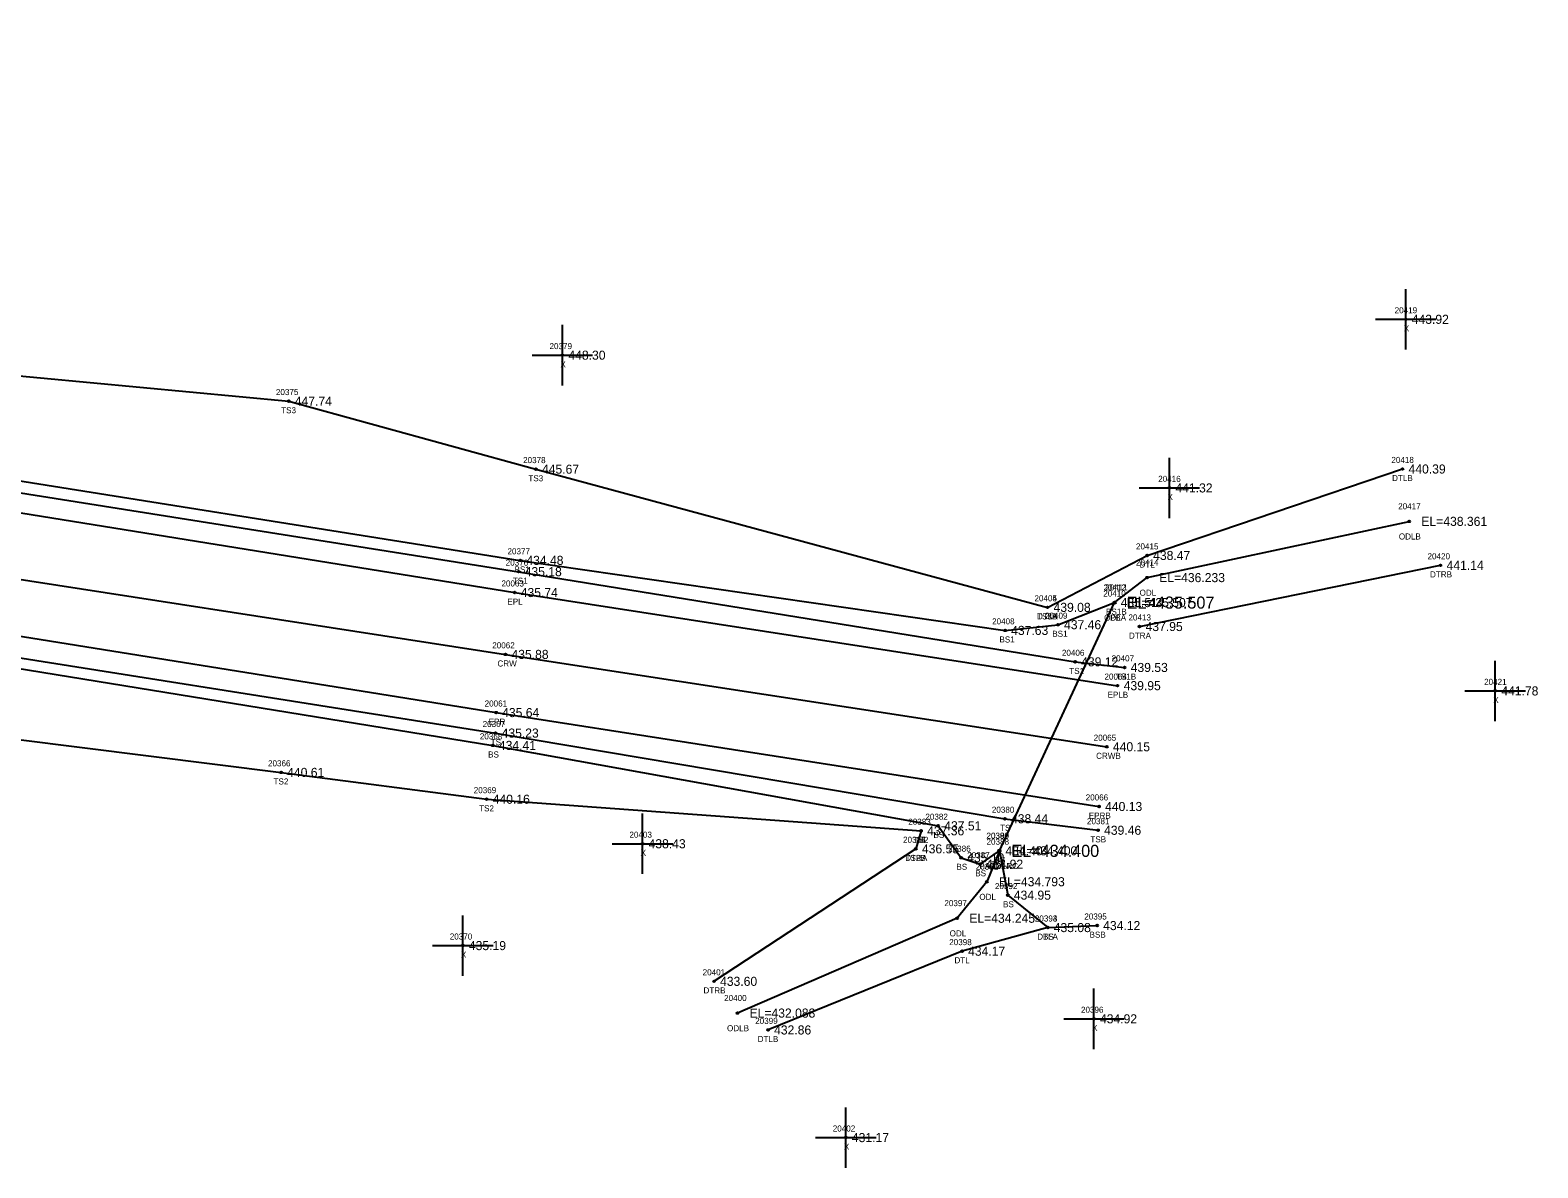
# Model space of a CAD drawing. Extents: x 1613184 to 1614731, y 770859 to 771868.
# Drawn here: x 1614482.1 to 1614731.4, y 771158.6 to 771346.7 of the extents above; entities that cross this region are included whole.
import ezdxf

# ---------------------------------------------------------------- set-up
doc = ezdxf.new("R2010")
doc.units = 0
for name, color, linetype in [('Default', 7, 'Continuous'), ('RD_DTM_BkLn1', 7, 'Continuous'), ('RD_DTM_BkLn2', 7, 'Continuous'), ('RD_DTM_BkLn_txCode', 7, 'Continuous'), ('RD_EX_DR_Pipe_txCode', 7, 'Continuous'), ('RD_EX_H2O', 7, 'Continuous'), ('RD_EX_H2O_txCode', 7, 'Continuous'), ('RD_EX_Misc', 7, 'Continuous'), ('RD_EX_Misc_txCode', 7, 'Continuous'), ('RD_EX_Road', 7, 'Continuous'), ('RD_EX_Road_txCode', 7, 'Continuous'), ('RD_EX_TX_H2O_ELEV', 7, 'Continuous'), ('RD_EX_TX_Misc_ELEV', 7, 'Continuous'), ('RD_EX_TX_Road_ELEV', 7, 'Continuous'), ('RD_HC_Survey_ELEV', 7, 'Continuous'), ('RD_HC_Survey_txCode', 7, 'Continuous'), ('RD_SMD_Locator', 7, 'Continuous'), ('RD_TX_Pipe_ElevEX', 7, 'Continuous')]:
    doc.layers.add(name, color=color, linetype=linetype)

msp = doc.modelspace()

# ---------------------------------------------------------------- linework, layer by layer
at = {"layer": 'Default'}
msp.add_line((1614642.36, 771211.01), (1614661.41, 771252.06), dxfattribs=at)
at = {"layer": 'RD_DTM_BkLn1'}
msp.add_lwpolyline([(1613965.11, 771336.88), (1614064.55, 771323.02), (1614163.88, 771306.86), (1614262.51, 771291.89), (1614361.57, 771275.2), (1614461.76, 771258.77), (1614560.71, 771243.49), (1614660.13, 771228.22)], dxfattribs=at)
at = {"layer": 'RD_DTM_BkLn2'}
for points in [[(1613964.19, 771322.73), (1613968.82, 771317.98), (1613995.59, 771312.64), (1614063.18, 771305.5), (1614161.48, 771291.91), (1614259.01, 771275.6), (1614358.23, 771261.08), (1614459.56, 771246.25), (1614559.08, 771230.48), (1614643.28, 771216.31), (1614658.67, 771214.41)], [(1613942.37, 771316.04), (1613958.6, 771307.1), (1613993.85, 771297.11), (1614061.98, 771289.14), (1614161.12, 771278.24), (1614255.97, 771263.05), (1614304.44, 771258.76), (1614327.58, 771260.25), (1614357.86, 771257.94), (1614459.3, 771244.57), (1614558.63, 771228.44), (1614632.25, 771215.15), (1614636.04, 771209.87), (1614639.16, 771208.8), (1614642.36, 771211.01), (1614643.75, 771203.68), (1614650.35, 771198.32), (1614658.52, 771198.65)], [(1614279.01, 771313.26), (1614281.2, 771317.14), (1614295.57, 771311.48), (1614364.56, 771299.51), (1614467.36, 771290.78), (1614524.89, 771285.37), (1614565.75, 771274.12), (1614650.32, 771251.27)], [(1614279.01, 771313.26), (1614280.58, 771310.17), (1614294.3, 771303.5), (1614363.28, 771288.72), (1614464.52, 771272.74), (1614562.89, 771257.17), (1614654.88, 771242.26), (1614663.07, 771241.33)], [(1614281.21, 771312.71), (1614294.52, 771307.09), (1614363.85, 771291.82), (1614464.84, 771274.67), (1614563.17, 771259.04), (1614643.31, 771247.46), (1614652.05, 771248.4), (1614661.41, 771252.06)], [(1614308.13, 771255.96), (1614327.93, 771256.05), (1614357.76, 771255.48), (1614457.77, 771232.22), (1614523.63, 771223.98), (1614557.61, 771219.54), (1614629.42, 771214.32), (1614628.56, 771211.34)]]:
    msp.add_lwpolyline(points, dxfattribs=at)
at = {"layer": 'RD_EX_H2O'}
for p, q in [((1614665.53, 771248.1), (1614715.29, 771258.22)), ((1614628.56, 771211.34), (1614595.19, 771189.43))]:
    msp.add_line(p, q, dxfattribs=at)
for points in [[(1614650.32, 771251.27), (1614666.78, 771259.85), (1614709, 771274.15)], [(1614661.41, 771252.06), (1614666.78, 771256.19), (1614710.12, 771265.49)], [(1614642.36, 771211.01), (1614640.3, 771205.9), (1614635.39, 771199.86), (1614599.06, 771184.18)], [(1614650.35, 771198.32), (1614636.19, 771194.41), (1614604.12, 771181.39)]]:
    msp.add_lwpolyline(points, dxfattribs=at)
at = {"layer": 'RD_EX_Misc'}
for p, q in [((1614709.53, 771293.9), (1614709.53, 771303.9)), ((1614704.53, 771298.9), (1614714.53, 771298.9)), ((1614570.12, 771287.97), (1614570.12, 771297.97)), ((1614565.12, 771292.97), (1614575.12, 771292.97)), ((1614670.47, 771266.02), (1614670.47, 771276.02)), ((1614665.47, 771271.02), (1614675.47, 771271.02)), ((1614724.33, 771232.45), (1614724.33, 771242.45)), ((1614719.33, 771237.45), (1614729.33, 771237.45)), ((1614583.37, 771207.18), (1614583.37, 771217.18)), ((1614578.37, 771212.18), (1614588.37, 771212.18)), ((1614553.67, 771190.34), (1614553.67, 771200.34)), ((1614548.67, 771195.34), (1614558.67, 771195.34)), ((1614657.99, 771178.23), (1614657.99, 771188.23)), ((1614652.99, 771183.23), (1614662.99, 771183.23)), ((1614616.98, 771158.59), (1614616.98, 771168.59)), ((1614611.98, 771163.59), (1614621.98, 771163.59))]:
    msp.add_line(p, q, dxfattribs=at)
at = {"layer": 'RD_EX_Road'}
for points in [[(1613966.21, 771346.72), (1614065.91, 771332.61), (1614166, 771316.74), (1614252.8, 771303.53), (1614264.27, 771301.76), (1614271.95, 771300.8), (1614363.43, 771285.99), (1614463.49, 771269.68), (1614562.24, 771253.72), (1614661.91, 771238.32)], [(1613963.41, 771324.71), (1614062.98, 771312.73), (1614162.48, 771297.04), (1614260.87, 771281.9), (1614360.23, 771265.95), (1614460.24, 771249.77), (1614559.17, 771233.87), (1614658.84, 771218.34)]]:
    msp.add_lwpolyline(points, dxfattribs=at)
at = {"layer": 'RD_SMD_Locator'}
for centre, radius in [((1614709.53, 771298.9), 0.15), ((1614570.12, 771292.97), 0.15), ((1614524.89, 771285.37), 0.15), ((1614565.75, 771274.12), 0.15), ((1614709, 771274.15), 0.15), ((1614670.47, 771271.02), 0.15), ((1614710.12, 771265.49), 0.15), ((1614563.17, 771259.04), 0.15), ((1614666.78, 771259.85), 0.15), ((1614562.89, 771257.17), 0.15), ((1614666.78, 771256.19), 0.15), ((1614715.29, 771258.22), 0.15), ((1614562.24, 771253.72), 0.15), ((1614650.32, 771251.27), 0.15), ((1614650.32, 771251.27), 0.15), ((1614661.41, 771252.06), 0.2), ((1614661.41, 771252.06), 0.15), ((1614661.41, 771252.06), 0.15), ((1614652.05, 771248.4), 0.15), ((1614643.31, 771247.46), 0.15), ((1614665.53, 771248.1), 0.15), ((1614560.71, 771243.49), 0.15), ((1614654.88, 771242.26), 0.15), ((1614663.07, 771241.33), 0.15), ((1614661.91, 771238.32), 0.15), ((1614724.33, 771237.45), 0.15), ((1614559.17, 771233.87), 0.15), ((1614558.63, 771228.44), 0.15), ((1614559.08, 771230.48), 0.15), ((1614660.13, 771228.22), 0.15), ((1614523.63, 771223.98), 0.15), ((1614557.61, 771219.54), 0.15), ((1614643.28, 771216.31), 0.15), ((1614658.84, 771218.34), 0.15), ((1614629.42, 771214.32), 0.15), ((1614632.25, 771215.15), 0.15), ((1614658.67, 771214.41), 0.15), ((1614583.37, 771212.18), 0.15), ((1614628.56, 771211.34), 0.15), ((1614628.56, 771211.34), 0.15), ((1614642.36, 771211.01), 0.2), ((1614642.36, 771211.01), 0.15), ((1614642.36, 771211.01), 0.15), ((1614636.04, 771209.87), 0.15), ((1614639.16, 771208.8), 0.15), ((1614640.3, 771205.9), 0.15), ((1614643.75, 771203.68), 0.15), ((1614635.39, 771199.86), 0.15), ((1614658.52, 771198.65), 0.15), ((1614650.35, 771198.32), 0.15), ((1614650.35, 771198.32), 0.15), ((1614553.67, 771195.34), 0.15), ((1614636.19, 771194.41), 0.15), ((1614595.19, 771189.43), 0.15), ((1614599.06, 771184.18), 0.15), ((1614604.12, 771181.39), 0.15), ((1614657.99, 771183.23), 0.15), ((1614616.98, 771163.59), 0.15)]:
    msp.add_circle(centre, radius, dxfattribs=at)

# ---------------------------------------------------------------- texts
at = {"layer": 'RD_DTM_BkLn_txCode'}
for s, p in [('20375', (1614522.77, 771286.37)), ('TS3', (1614523.64, 771283.37)), ('20378', (1614563.63, 771275.12)), ('TS3', (1614564.5, 771272.12)), ('20377', (1614561.05, 771260.04)), ('20376', (1614560.75, 771258.17)), ('TS1', (1614561.93, 771255.17)), ('BS1', (1614562.22, 771257.04)), ('20410', (1614659.54, 771253.06)), ('20404', (1614648.16, 771252.27)), ('BS1B', (1614659.99, 771250.06)), ('20408', (1614641.16, 771248.46)), ('TS3B', (1614648.6, 771249.27)), ('20409', (1614649.9, 771249.4)), ('BS1', (1614642.37, 771245.46)), ('BS1', (1614651.11, 771246.4)), ('20406', (1614652.7, 771243.26)), ('TS1', (1614653.92, 771240.26)), ('20407', (1614660.91, 771242.33)), ('TS1B', (1614661.63, 771239.33)), ('20367', (1614556.94, 771231.48)), ('20368', (1614556.48, 771229.44)), ('TS', (1614558.28, 771228.48)), ('BS', (1614557.85, 771226.44)), ('20366', (1614521.46, 771224.98)), ('TS2', (1614522.38, 771221.98)), ('20369', (1614555.47, 771220.54)), ('TS2', (1614556.36, 771217.54)), ('20383', (1614627.3, 771215.32)), ('20382', (1614630.13, 771216.15)), ('20380', (1614641.12, 771217.31)), ('20381', (1614656.84, 771215.41)), ('BS', (1614631.47, 771213.15)), ('TS', (1614642.48, 771214.31)), ('20384', (1614626.44, 771212.34)), ('TS2', (1614628.17, 771212.32)), ('20386', (1614633.9, 771210.87)), ('20388', (1614640.24, 771212.01)), ('TSB', (1614657.41, 771212.41)), ('TS2B', (1614626.84, 771209.34)), ('BS', (1614635.26, 771207.87)), ('20387', (1614637.05, 771209.8)), ('BS', (1614641.58, 771209.01)), ('BS', (1614638.38, 771206.8)), ('20392', (1614641.63, 771204.68)), ('BS', (1614642.97, 771201.68)), ('20393', (1614648.23, 771199.32)), ('20395', (1614656.4, 771199.65)), ('BS', (1614649.57, 771196.32)), ('BSB', (1614657.27, 771196.65))]:
    msp.add_text(s, height=1, dxfattribs=at).set_placement(p)
at = {"layer": 'RD_EX_DR_Pipe_txCode'}
for s, p in [('20411', (1614659.86, 771254.06)), ('PB', (1614660.63, 771249.06)), ('20390', (1614640.21, 771213.01)), ('PA 18" RC', (1614639.03, 771208.01))]:
    msp.add_text(s, height=1, dxfattribs=at).set_placement(p)
at = {"layer": 'RD_EX_H2O_txCode'}
for s, p in [('20418', (1614707.16, 771275.15)), ('DTLB', (1614707.28, 771272.15)), ('20417', (1614708.29, 771267.49)), ('ODLB', (1614708.4, 771262.49)), ('20415', (1614664.94, 771260.85)), ('20414', (1614664.95, 771258.19)), ('DTL', (1614665.53, 771257.85)), ('20420', (1614713.14, 771259.22)), ('DTRB', (1614713.55, 771256.22)), ('20412', (1614659.58, 771254.06)), ('ODL', (1614665.54, 771253.19)), ('20405', (1614648.16, 771252.27)), ('DTLA', (1614648.58, 771249.27)), ('ODLA', (1614659.68, 771249.06)), ('20413', (1614663.7, 771249.1)), ('DTRA', (1614663.78, 771246.1)), ('20389', (1614640.24, 771213.01)), ('20385', (1614626.44, 771212.34)), ('DTRA', (1614626.8, 771209.34)), ('20391', (1614638.46, 771207.9)), ('ODLA', (1614640.63, 771208.01)), ('ODL', (1614639.05, 771202.9)), ('20397', (1614633.27, 771201.86)), ('20394', (1614648.23, 771199.32)), ('20398', (1614634.07, 771195.41)), ('ODL', (1614634.14, 771196.86)), ('DTLA', (1614648.62, 771196.32)), ('20401', (1614593.31, 771190.43)), ('DTL', (1614634.94, 771192.41)), ('DTRB', (1614593.45, 771187.43)), ('20400', (1614596.86, 771186.18)), ('ODLB', (1614597.34, 771181.18)), ('20399', (1614602, 771182.39)), ('DTLB', (1614602.4, 771179.39))]:
    msp.add_text(s, height=1, dxfattribs=at).set_placement(p)
at = {"layer": 'RD_EX_Misc_txCode'}
for s, p in [('20419', (1614707.7, 771299.9)), ('X', (1614709.22, 771296.9)), ('20379', (1614568, 771293.97)), ('X', (1614569.8, 771290.97)), ('20416', (1614668.62, 771272.02)), ('X', (1614670.16, 771269.02)), ('20421', (1614722.49, 771238.45)), ('X', (1614724.01, 771235.45)), ('20403', (1614581.21, 771213.18)), ('X', (1614583.06, 771210.18)), ('20370', (1614551.51, 771196.34)), ('X', (1614553.35, 771193.34)), ('20396', (1614655.85, 771184.23)), ('X', (1614657.68, 771181.23)), ('20402', (1614614.82, 771164.59)), ('X', (1614616.66, 771161.59))]:
    msp.add_text(s, height=1, dxfattribs=at).set_placement(p)
at = {"layer": 'RD_EX_Road_txCode'}
for s, p in [('20063', (1614560.05, 771254.72)), ('EPL', (1614561.03, 771251.72)), ('20064', (1614659.73, 771239.32)), ('EPLB', (1614660.24, 771236.32)), ('20061', (1614557.27, 771234.87)), ('EPR', (1614557.94, 771231.87)), ('20066', (1614656.63, 771219.34)), ('EPRB', (1614657.14, 771216.34))]:
    msp.add_text(s, height=1, dxfattribs=at).set_placement(p)
at = {"layer": 'RD_EX_TX_H2O_ELEV'}
for s, p in [('440.39', (1614710, 771273.4)), ('EL=438.361', (1614712.12, 771264.74)), ('438.47', (1614667.78, 771259.1)), ('441.14', (1614716.29, 771257.47)), ('EL=436.233', (1614668.78, 771255.44)), ('439.08', (1614651.32, 771250.52)), ('EL=435.507', (1614663.41, 771251.31)), ('437.95', (1614666.53, 771247.35)), ('436.55', (1614629.56, 771210.59)), ('EL=434.400', (1614644.36, 771210.26)), ('EL=434.793', (1614642.3, 771205.15)), ('EL=434.245', (1614637.39, 771199.11)), ('435.08', (1614651.35, 771197.57)), ('434.17', (1614637.19, 771193.66)), ('433.60', (1614596.19, 771188.68)), ('EL=432.088', (1614601.06, 771183.43)), ('432.86', (1614605.12, 771180.64))]:
    msp.add_text(s, height=1.5, dxfattribs=at).set_placement(p)
at = {"layer": 'RD_EX_TX_Misc_ELEV'}
for s, p in [('443.92', (1614710.53, 771298.15)), ('448.30', (1614571.12, 771292.22)), ('447.74', (1614525.89, 771284.62)), ('445.67', (1614566.75, 771273.37)), ('441.32', (1614671.47, 771270.27)), ('434.48', (1614564.17, 771258.29)), ('435.18', (1614563.89, 771256.42)), ('439.08', (1614651.32, 771250.52)), ('435.51', (1614662.41, 771251.31)), ('437.46', (1614653.05, 771247.65)), ('437.63', (1614644.31, 771246.71)), ('439.12', (1614655.88, 771241.51)), ('439.53', (1614664.07, 771240.58)), ('441.78', (1614725.33, 771236.7)), ('435.23', (1614560.08, 771229.73)), ('434.41', (1614559.63, 771227.69)), ('440.61', (1614524.63, 771223.23)), ('440.16', (1614558.61, 771218.79)), ('438.44', (1614644.28, 771215.56)), ('437.36', (1614630.42, 771213.57)), ('437.51', (1614633.25, 771214.4)), ('439.46', (1614659.67, 771213.66)), ('438.43', (1614584.37, 771211.43)), ('436.55', (1614629.56, 771210.59)), ('434.40', (1614643.36, 771210.26)), ('435.10', (1614637.04, 771209.12)), ('434.92', (1614640.16, 771208.05)), ('434.95', (1614644.75, 771202.93)), ('435.08', (1614651.35, 771197.57)), ('434.12', (1614659.52, 771197.9)), ('435.19', (1614554.67, 771194.59)), ('434.92', (1614658.99, 771182.48)), ('431.17', (1614617.98, 771162.84))]:
    msp.add_text(s, height=1.5, dxfattribs=at).set_placement(p)
at = {"layer": 'RD_EX_TX_Road_ELEV'}
for s, p in [('435.74', (1614563.24, 771252.97)), ('439.95', (1614662.91, 771237.57)), ('435.64', (1614560.17, 771233.12)), ('440.13', (1614659.84, 771217.59))]:
    msp.add_text(s, height=1.5, dxfattribs=at).set_placement(p)
at = {"layer": 'RD_HC_Survey_ELEV'}
for s, p in [('435.88', (1614561.71, 771242.74)), ('440.15', (1614661.13, 771227.47))]:
    msp.add_text(s, height=1.5, dxfattribs=at).set_placement(p)
at = {"layer": 'RD_HC_Survey_txCode'}
for s, p in [('20062', (1614558.53, 771244.49)), ('CRW', (1614559.39, 771241.49)), ('20065', (1614657.95, 771229.22)), ('CRWB', (1614658.35, 771226.22))]:
    msp.add_text(s, height=1, dxfattribs=at).set_placement(p)
at = {"layer": 'RD_TX_Pipe_ElevEX'}
for s, p in [('EL=435.507', (1614663.41, 771251.06)), ('EL=434.400', (1614644.36, 771210.01))]:
    msp.add_text(s, height=2, dxfattribs=at).set_placement(p)

doc.saveas('drawing.dxf')
